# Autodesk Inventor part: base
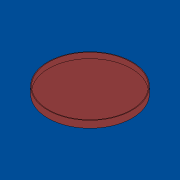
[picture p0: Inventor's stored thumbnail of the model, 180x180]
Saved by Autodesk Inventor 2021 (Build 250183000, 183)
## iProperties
Created: 2020-10
Part Number: base
Material: Generic
Document SubType Name: Modeling
Designer: Stu
Density: 1 g/cm^3
Appearance: Default
Author: Stu
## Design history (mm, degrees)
sketch "Sketch1"
  geometry: C1 r 381 at (0, 0); 1 further point
  constraints: 1 centre point, 1 coincident
  dimensions: "d0" = 762 diameter of C1
extrude "Extrusion1" new body sketch "Sketch1" distance "d1" = 12.7; taper "d2" = 0 deg
sketch "Sketch2"
  geometry: C1 r 381 at (0, 0) reference; C2 r 387.35 at (0, 0); 1 further point
  constraints: 1 centre point, 1 coincident
  dimensions: "d3" = 774.7 diameter of C2
extrude "Extrusion2" join sketch "Sketch2" distance "d4" = 63.5; taper "d5" = 0 deg
body "Solid1"
